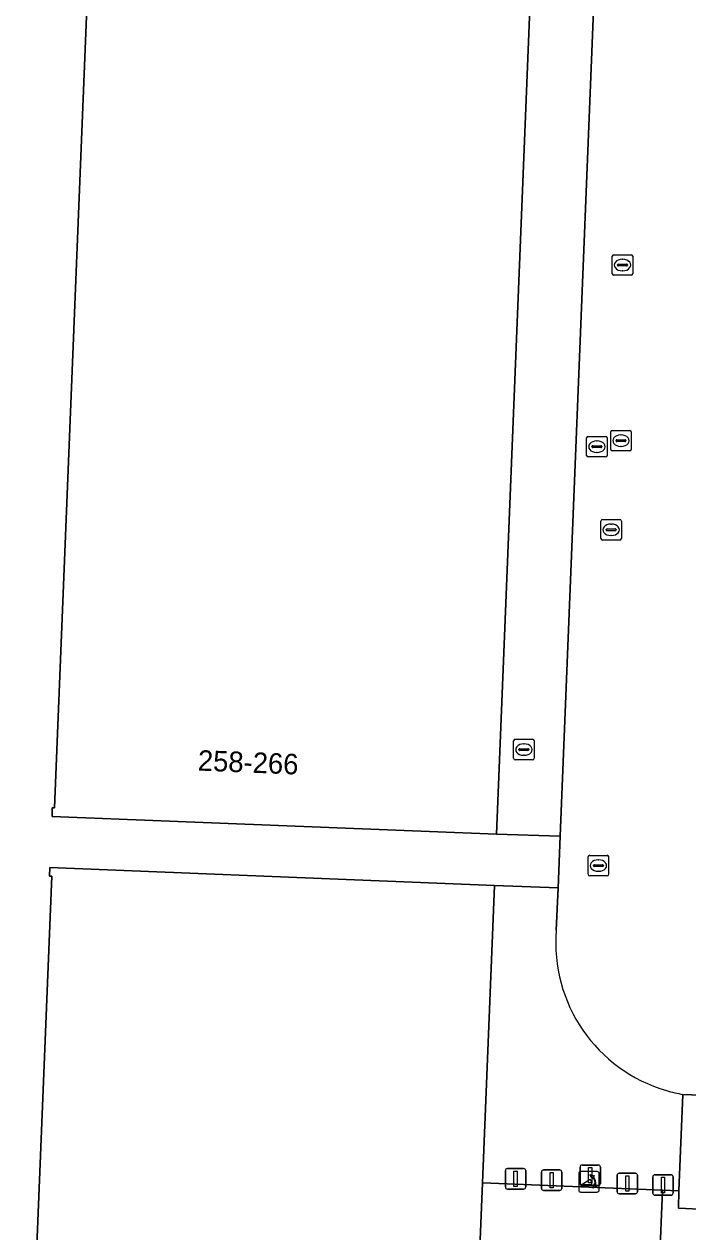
# Model space of a CAD drawing. Extents: x 160888 to 161385, y 386490 to 386908.
# Drawn here: x 161191.2 to 161223.6, y 386584.9 to 386643.8 of the extents above; entities that cross this region are included whole.
import ezdxf

# ---------------------------------------------------------------- set-up
doc = ezdxf.new("R2010")
doc.units = 0
for name, color, linetype in [('IMGEO_Afsluitpaal', 7, 'Continuous'), ('IMGEO_Brandkraan', 7, 'Continuous'), ('IMGEO_Groenvoorziening', 7, 'Continuous'), ('IMGEO_Haag', 7, 'Continuous'), ('IMGEO_Kolk', 7, 'Continuous'), ('IMGEO_Pand', 7, 'Continuous'), ('IMGEO_Pand_nummerreeks', 7, 'Continuous'), ('IMGEO_Poller', 7, 'Continuous'), ('IMGEO_Rijbaan_lokaal_open', 7, 'Continuous'), ('IMGEO_Rioolput', 7, 'Continuous'), ('IMGEO_Voetgangersgebied_open', 7, 'Continuous'), ('IMGEO_Voetpad_open', 7, 'Continuous')]:
    doc.layers.add(name, color=color, linetype=linetype)

msp = doc.modelspace()

# ---------------------------------------------------------------- linework, layer by layer
at = {"layer": 'IMGEO_Afsluitpaal'}
for p, q in [((161214.773, 386588.001), (161215.563, 386588.001)), ((161215.563, 386588.001), (161214.773, 386588.001)), ((161218.315, 386587.271), (161218.315, 386588.071)), ((161218.315, 386588.071), (161218.315, 386587.271)), ((161218.415, 386588.171), (161219.205, 386588.171)), ((161219.205, 386588.171), (161218.415, 386588.171)), ((161219.305, 386588.071), (161219.305, 386587.271)), ((161219.305, 386587.271), (161219.305, 386588.071)), ((161214.673, 386587.101), (161214.673, 386587.901)), ((161214.673, 386587.901), (161214.673, 386587.101)), ((161215.663, 386587.901), (161215.663, 386587.101)), ((161215.663, 386587.101), (161215.663, 386587.901)), ((161216.431, 386587.031), (161216.431, 386587.831)), ((161216.431, 386587.831), (161216.431, 386587.031)), ((161216.531, 386587.931), (161217.321, 386587.931)), ((161217.321, 386587.931), (161216.531, 386587.931)), ((161217.421, 386587.831), (161217.421, 386587.031)), ((161217.421, 386587.031), (161217.421, 386587.831)), ((161220.124, 386586.872), (161220.124, 386587.672)), ((161220.124, 386587.672), (161220.124, 386586.872)), ((161220.224, 386587.772), (161221.014, 386587.772)), ((161221.014, 386587.772), (161220.224, 386587.772)), ((161221.114, 386587.672), (161221.114, 386586.872)), ((161221.114, 386586.872), (161221.114, 386587.672)), ((161221.865, 386586.798), (161221.865, 386587.598)), ((161221.865, 386587.598), (161221.865, 386586.798)), ((161221.965, 386587.698), (161222.755, 386587.698)), ((161222.755, 386587.698), (161221.965, 386587.698)), ((161222.855, 386587.598), (161222.855, 386586.798)), ((161222.855, 386586.798), (161222.855, 386587.598)), ((161215.563, 386587.001), (161214.773, 386587.001)), ((161214.773, 386587.001), (161215.563, 386587.001)), ((161217.321, 386586.931), (161216.531, 386586.931)), ((161216.531, 386586.931), (161217.321, 386586.931)), ((161219.205, 386587.171), (161218.415, 386587.171)), ((161218.415, 386587.171), (161219.205, 386587.171)), ((161221.014, 386586.772), (161220.224, 386586.772)), ((161220.224, 386586.772), (161221.014, 386586.772)), ((161222.755, 386586.698), (161221.965, 386586.698)), ((161221.965, 386586.698), (161222.755, 386586.698))]:
    msp.add_line(p, q, dxfattribs=at)
for points in [[(161218.735, 386588.046), (161218.885, 386588.046), (161218.885, 386587.296), (161218.735, 386587.296), (161218.735, 386588.046)], [(161215.093, 386587.876), (161215.243, 386587.876), (161215.243, 386587.126), (161215.093, 386587.126), (161215.093, 386587.876)], [(161216.851, 386587.806), (161217.001, 386587.806), (161217.001, 386587.056), (161216.851, 386587.056), (161216.851, 386587.806)], [(161220.544, 386587.647), (161220.694, 386587.647), (161220.694, 386586.897), (161220.544, 386586.897), (161220.544, 386587.647)], [(161222.285, 386587.573), (161222.435, 386587.573), (161222.435, 386586.823), (161222.285, 386586.823), (161222.285, 386587.573)]]:
    msp.add_lwpolyline(points, dxfattribs=at)
for centre, start, end in [((161214.773, 386587.901), 90, 180), ((161214.773, 386587.901), 90, 180), ((161215.563, 386587.901), 0, 90), ((161215.563, 386587.901), 360, 90), ((161218.415, 386588.071), 90, 180), ((161218.415, 386588.071), 90, 180), ((161219.205, 386588.071), 0, 90), ((161219.205, 386588.071), 360, 90), ((161216.531, 386587.831), 90, 180), ((161216.531, 386587.831), 90, 180), ((161217.321, 386587.831), 0, 90), ((161217.321, 386587.831), 360, 90), ((161220.224, 386587.672), 90, 180), ((161220.224, 386587.672), 90, 180), ((161221.014, 386587.672), 0, 90), ((161221.014, 386587.672), 360, 90), ((161221.965, 386587.598), 90, 180), ((161221.965, 386587.598), 90, 180), ((161222.755, 386587.598), 0, 90), ((161222.755, 386587.598), 360, 90), ((161214.773, 386587.101), 180, 270), ((161214.773, 386587.101), 180, 270), ((161215.563, 386587.101), 270, 0), ((161215.563, 386587.101), 270, 0), ((161216.531, 386587.031), 180, 270), ((161216.531, 386587.031), 180, 270), ((161217.321, 386587.031), 270, 0), ((161217.321, 386587.031), 270, 0), ((161218.415, 386587.271), 180, 270), ((161218.415, 386587.271), 180, 270), ((161219.205, 386587.271), 270, 0), ((161219.205, 386587.271), 270, 0), ((161220.224, 386586.872), 180, 270), ((161220.224, 386586.872), 180, 270), ((161221.014, 386586.872), 270, 0), ((161221.014, 386586.872), 270, 0), ((161221.965, 386586.798), 180, 270), ((161221.965, 386586.798), 180, 270), ((161222.755, 386586.798), 270, 0), ((161222.755, 386586.798), 270, 0)]:
    msp.add_arc(centre, 0.1, start, end, dxfattribs=at)
at = {"layer": 'IMGEO_Brandkraan'}
for p, q in [((161215.075, 386608.011), (161215.075, 386608.863)), ((161215.15, 386608.937), (161216.002, 386608.937)), ((161215.563, 386608.717), (161215.588, 386608.717)), ((161216.076, 386608.863), (161216.076, 386608.011)), ((161215.334, 386608.431), (161215.334, 386608.443)), ((161215.772, 386608.394), (161215.374, 386608.394)), ((161215.377, 386608.48), (161215.775, 386608.48)), ((161215.586, 386608.157), (161215.561, 386608.157)), ((161215.818, 386608.443), (161215.818, 386608.431)), ((161216.002, 386607.937), (161215.15, 386607.937))]:
    msp.add_line(p, q, dxfattribs=at)
for points in [[(161215.075, 386608.011), (161215.075, 386608.863)], [(161215.15, 386608.937), (161216.002, 386608.937)], [(161216.076, 386608.863), (161216.076, 386608.011)], [(161216.002, 386607.937), (161215.15, 386607.937)]]:
    msp.add_lwpolyline(points, dxfattribs=at)
for centre, radius, start, end in [((161215.152, 386608.861), 0.0765, 91.55205, 178.44795), ((161215.152, 386608.861), 0.0765, 91.55205, 178.44795), ((161216, 386608.861), 0.0765, 1.55205, 88.44795), ((161216, 386608.861), 0.0765, 1.55205, 88.44795), ((161215.152, 386608.013), 0.0765, 181.55205, 268.44795), ((161215.152, 386608.013), 0.0765, 181.55205, 268.44795), ((161215.374, 386608.44), 0.0403, 85.87752, 175.75265), ((161215.371, 386608.43), 0.0366, 178.93798, 274.71019), ((161215.775, 386608.437), 0.043, 264.86636, 352.45326), ((161215.779, 386608.442), 0.0386, 1.73085, 96.63898), ((161216, 386608.013), 0.0765, 271.55205, 358.44795), ((161216, 386608.013), 0.0765, 271.55205, 358.44795)]:
    msp.add_arc(centre, radius, start, end, dxfattribs=at)
for centre, major_axis, ratio, start_param, end_param in [((161215.562, 386608.437), (-0.387, 0.002), 0.722429, 4.712389, 7.853982), ((161215.587, 386608.437), (-0.39, 0.002), 0.717154, 1.570796, 4.712389)]:
    msp.add_ellipse(centre, major_axis=major_axis, ratio=ratio, start_param=start_param, end_param=end_param, dxfattribs=at)
at = {"layer": 'IMGEO_Groenvoorziening'}
msp.add_lwpolyline([(161225.845, 386591.51), (161223.337, 386591.617), (161223.136, 386586.912), (161223.119, 386586.063), (161225.814, 386585.935), (161226.578, 386585.899), (161226.59, 386586.509)], dxfattribs=at)
at = {"layer": 'IMGEO_Haag'}
msp.add_lwpolyline([(161225.845, 386591.51), (161223.337, 386591.617), (161223.136, 386586.912), (161223.119, 386586.063), (161225.814, 386585.935), (161226.578, 386585.899), (161226.59, 386586.509)], dxfattribs=at)
at = {"layer": 'IMGEO_Kolk'}
for p, q in [((161219.886, 386631.645), (161219.886, 386632.497)), ((161219.961, 386632.571), (161220.813, 386632.571)), ((161220.374, 386632.351), (161220.399, 386632.351)), ((161220.887, 386632.497), (161220.887, 386631.645)), ((161220.145, 386632.065), (161220.145, 386632.077)), ((161220.583, 386632.028), (161220.185, 386632.028)), ((161220.188, 386632.114), (161220.586, 386632.114)), ((161220.397, 386631.791), (161220.372, 386631.791)), ((161220.629, 386632.077), (161220.629, 386632.065)), ((161220.813, 386631.571), (161219.961, 386631.571)), ((161219.331, 386618.732), (161219.331, 386619.584)), ((161219.406, 386619.658), (161220.258, 386619.658)), ((161219.633, 386619.201), (161220.031, 386619.201)), ((161219.819, 386619.438), (161219.844, 386619.438)), ((161220.332, 386619.584), (161220.332, 386618.732)), ((161220.258, 386618.658), (161219.406, 386618.658)), ((161219.59, 386619.152), (161219.59, 386619.164)), ((161220.028, 386619.115), (161219.63, 386619.115)), ((161219.842, 386618.878), (161219.817, 386618.878)), ((161220.074, 386619.164), (161220.074, 386619.152)), ((161218.71, 386602.352), (161218.71, 386603.204)), ((161218.785, 386603.278), (161219.637, 386603.278)), ((161218.969, 386602.772), (161218.969, 386602.784)), ((161219.407, 386602.735), (161219.009, 386602.735)), ((161219.012, 386602.821), (161219.41, 386602.821)), ((161219.198, 386603.058), (161219.223, 386603.058)), ((161219.453, 386602.784), (161219.453, 386602.772)), ((161219.711, 386603.204), (161219.711, 386602.352)), ((161219.637, 386602.278), (161218.785, 386602.278)), ((161219.221, 386602.498), (161219.196, 386602.498))]:
    msp.add_line(p, q, dxfattribs=at)
for points in [[(161219.886, 386631.645), (161219.886, 386632.497)], [(161219.961, 386632.571), (161220.813, 386632.571)], [(161220.887, 386632.497), (161220.887, 386631.645)], [(161220.813, 386631.571), (161219.961, 386631.571)], [(161219.331, 386618.732), (161219.331, 386619.584)], [(161219.406, 386619.658), (161220.258, 386619.658)], [(161220.332, 386619.584), (161220.332, 386618.732)], [(161220.258, 386618.658), (161219.406, 386618.658)], [(161218.71, 386602.352), (161218.71, 386603.204)], [(161218.785, 386603.278), (161219.637, 386603.278)], [(161219.711, 386603.204), (161219.711, 386602.352)], [(161219.637, 386602.278), (161218.785, 386602.278)]]:
    msp.add_lwpolyline(points, dxfattribs=at)
for centre, radius, start, end in [((161219.963, 386632.495), 0.0765, 91.55205, 178.44795), ((161219.963, 386632.495), 0.0765, 91.55205, 178.44795), ((161220.811, 386632.495), 0.0765, 1.55205, 88.44795), ((161220.811, 386632.495), 0.0765, 1.55205, 88.44795), ((161219.963, 386631.647), 0.0765, 181.55205, 268.44795), ((161219.963, 386631.647), 0.0765, 181.55205, 268.44795), ((161220.185, 386632.074), 0.0403, 85.87752, 175.75265), ((161220.182, 386632.064), 0.0366, 178.93798, 274.71019), ((161220.586, 386632.071), 0.043, 264.86636, 352.45326), ((161220.59, 386632.076), 0.0386, 1.73085, 96.63898), ((161220.811, 386631.647), 0.0765, 271.55205, 358.44795), ((161220.811, 386631.647), 0.0765, 271.55205, 358.44795), ((161219.408, 386619.582), 0.0765, 91.55205, 178.44795), ((161219.408, 386619.582), 0.0765, 91.55205, 178.44795), ((161219.63, 386619.161), 0.0403, 85.87752, 175.75265), ((161220.035, 386619.163), 0.0386, 1.73085, 96.63898), ((161220.256, 386619.582), 0.0765, 1.55205, 88.44795), ((161220.256, 386619.582), 0.0765, 1.55205, 88.44795), ((161219.408, 386618.734), 0.0765, 181.55205, 268.44795), ((161219.408, 386618.734), 0.0765, 181.55205, 268.44795), ((161219.627, 386619.151), 0.0366, 178.93798, 274.71019), ((161220.031, 386619.158), 0.043, 264.86636, 352.45326), ((161220.256, 386618.734), 0.0765, 271.55205, 358.44795), ((161220.256, 386618.734), 0.0765, 271.55205, 358.44795), ((161218.787, 386603.202), 0.0765, 91.55205, 178.44795), ((161218.787, 386603.202), 0.0765, 91.55205, 178.44795), ((161219.009, 386602.781), 0.0403, 85.87752, 175.75265), ((161219.006, 386602.771), 0.0366, 178.93798, 274.71019), ((161219.41, 386602.778), 0.043, 264.86636, 352.45326), ((161219.414, 386602.783), 0.0386, 1.73085, 96.63898), ((161219.635, 386603.202), 0.0765, 1.55205, 88.44795), ((161219.635, 386603.202), 0.0765, 1.55205, 88.44795), ((161218.787, 386602.354), 0.0765, 181.55205, 268.44795), ((161218.787, 386602.354), 0.0765, 181.55205, 268.44795), ((161219.635, 386602.354), 0.0765, 271.55205, 358.44795), ((161219.635, 386602.354), 0.0765, 271.55205, 358.44795)]:
    msp.add_arc(centre, radius, start, end, dxfattribs=at)
for centre, major_axis, ratio, start_param, end_param in [((161220.373, 386632.071), (-0.387, 0.002), 0.722429, 4.712389, 7.853982), ((161220.398, 386632.071), (-0.39, 0.002), 0.717154, 1.570796, 4.712389), ((161219.818, 386619.158), (-0.387, 0.002), 0.722429, 4.712389, 7.853982), ((161219.843, 386619.158), (-0.39, 0.002), 0.717154, 1.570796, 4.712389), ((161219.197, 386602.778), (-0.387, 0.002), 0.722429, 4.712389, 7.853982), ((161219.222, 386602.778), (-0.39, 0.002), 0.717154, 1.570796, 4.712389)]:
    msp.add_ellipse(centre, major_axis=major_axis, ratio=ratio, start_param=start_param, end_param=end_param, dxfattribs=at)
at = {"layer": 'IMGEO_Pand'}
for points in [[(161194.188, 386645.434), (161194.288, 386645.43), (161192.672, 386605.589), (161192.572, 386605.592), (161192.56, 386605.179), (161214.242, 386604.304), (161215.889, 386644.972), (161194.205, 386645.849)], [(161191.198, 386569.006), (161204.671, 386568.461), (161212.673, 386568.138), (161213.252, 386579.772), (161213.556, 386587.296), (161214.141, 386601.806), (161192.456, 386602.678), (161192.441, 386602.269), (161192.541, 386602.265)]]:
    msp.add_lwpolyline(points, close=True, dxfattribs=at)
at = {"layer": 'IMGEO_Poller'}
for p, q in [((161218.251, 386587.758), (161218.251, 386586.951)), ((161218.251, 386587.758), (161218.251, 386586.951)), ((161219.153, 386587.853), (161218.345, 386587.853)), ((161219.153, 386587.853), (161218.345, 386587.853)), ((161219.247, 386586.951), (161219.247, 386587.758)), ((161219.247, 386586.951), (161219.247, 386587.758)), ((161218.345, 386586.856), (161219.153, 386586.856)), ((161218.345, 386586.856), (161219.153, 386586.856))]:
    msp.add_line(p, q, dxfattribs=at)
for points in [[(161218.886, 386587.209), (161218.373, 386587.209), (161218.803, 386587.484)], [(161218.93, 386587.582), (161218.918, 386587.509), (161218.793, 386587.714)], [(161218.793, 386587.714), (161219.024, 386587.648), (161218.953, 386587.616)], [(161218.946, 386587.037), (161219.012, 386587.268), (161219.042, 386587.2)], [(161219.078, 386587.173), (161219.15, 386587.162), (161218.946, 386587.037)]]:
    msp.add_lwpolyline(points, dxfattribs=at)
for centre, radius, start, end in [((161218.345, 386587.758), 0.0946, 90, 180), ((161218.345, 386587.758), 0.0946, 90, 180), ((161218.558, 386587.259), 0.332, 351.32473, 42.4854), ((161218.572, 386587.269), 0.476, 351.75274, 41.16905), ((161218.572, 386587.269), 0.516, 349.35686, 42.29123), ((161219.153, 386587.758), 0.0946, 0, 90), ((161219.153, 386587.758), 0.0946, 0, 90), ((161218.345, 386586.951), 0.0946, 180, 270), ((161218.345, 386586.951), 0.0946, 180, 270), ((161219.153, 386586.951), 0.0946, 270, 0), ((161219.153, 386586.951), 0.0946, 270, 0)]:
    msp.add_arc(centre, radius, start, end, dxfattribs=at)
at = {"layer": 'IMGEO_Rijbaan_lokaal_open'}
for points in [[(161219.977, 386669.302), (161219.091, 386647.411), (161218.989, 386644.89), (161217.342, 386604.22), (161217.24, 386601.701), (161217.156, 386599.626)], [(161223.337, 386591.617), (161225.845, 386591.51), (161236.29, 386591.113), (161238.207, 386591.047), (161244.276, 386590.775), (161248.771, 386590.62), (161250.704, 386590.546), (161252.339, 386590.479), (161258.277, 386590.35), (161258.463, 386596.234), (161254.664, 386596.392), (161234.495, 386597.192), (161230, 386597.363)]]:
    msp.add_lwpolyline(points, dxfattribs=at)
for centre, radius, start, end in [((161224.629, 386599.004), 7.499, 175.24232, 253.73554), ((161224.643, 386599.059), 7.556, 253.75499, 260.04871)]:
    msp.add_arc(centre, radius, start, end, dxfattribs=at)
at = {"layer": 'IMGEO_Rioolput'}
for p, q in [((161219.81, 386623.079), (161219.81, 386623.931)), ((161219.885, 386624.005), (161220.737, 386624.005)), ((161220.811, 386623.931), (161220.811, 386623.079)), ((161218.636, 386622.786), (161218.636, 386623.638)), ((161218.711, 386623.712), (161219.563, 386623.712)), ((161219.124, 386623.492), (161219.149, 386623.492)), ((161219.637, 386623.638), (161219.637, 386622.786)), ((161220.069, 386623.499), (161220.069, 386623.511)), ((161220.507, 386623.462), (161220.109, 386623.462)), ((161220.112, 386623.548), (161220.51, 386623.548)), ((161220.298, 386623.785), (161220.323, 386623.785)), ((161220.553, 386623.511), (161220.553, 386623.499)), ((161218.895, 386623.206), (161218.895, 386623.218)), ((161219.333, 386623.169), (161218.935, 386623.169)), ((161218.938, 386623.255), (161219.336, 386623.255)), ((161219.147, 386622.932), (161219.122, 386622.932)), ((161219.379, 386623.218), (161219.379, 386623.206)), ((161220.737, 386623.005), (161219.885, 386623.005)), ((161220.321, 386623.225), (161220.296, 386623.225)), ((161219.563, 386622.712), (161218.711, 386622.712))]:
    msp.add_line(p, q, dxfattribs=at)
for points in [[(161219.81, 386623.079), (161219.81, 386623.931)], [(161219.885, 386624.005), (161220.737, 386624.005)], [(161220.811, 386623.931), (161220.811, 386623.079)], [(161218.636, 386622.786), (161218.636, 386623.638)], [(161218.711, 386623.712), (161219.563, 386623.712)], [(161219.637, 386623.638), (161219.637, 386622.786)], [(161220.737, 386623.005), (161219.885, 386623.005)], [(161219.563, 386622.712), (161218.711, 386622.712)]]:
    msp.add_lwpolyline(points, dxfattribs=at)
for centre, radius, start, end in [((161219.887, 386623.929), 0.0765, 91.55205, 178.44795), ((161219.887, 386623.929), 0.0765, 91.55205, 178.44795), ((161220.735, 386623.929), 0.0765, 1.55205, 88.44795), ((161220.735, 386623.929), 0.0765, 1.55205, 88.44795), ((161218.713, 386623.636), 0.0765, 91.55205, 178.44795), ((161218.713, 386623.636), 0.0765, 91.55205, 178.44795), ((161219.561, 386623.636), 0.0765, 1.55205, 88.44795), ((161219.561, 386623.636), 0.0765, 1.55205, 88.44795), ((161220.109, 386623.508), 0.0403, 85.87752, 175.75265), ((161220.106, 386623.498), 0.0366, 178.93798, 274.71019), ((161220.51, 386623.505), 0.043, 264.86636, 352.45326), ((161220.514, 386623.51), 0.0386, 1.73085, 96.63898), ((161218.713, 386622.788), 0.0765, 181.55205, 268.44795), ((161218.713, 386622.788), 0.0765, 181.55205, 268.44795), ((161218.935, 386623.215), 0.0403, 85.87752, 175.75265), ((161218.932, 386623.205), 0.0366, 178.93798, 274.71019), ((161219.336, 386623.212), 0.043, 264.86636, 352.45326), ((161219.34, 386623.217), 0.0386, 1.73085, 96.63898), ((161219.561, 386622.788), 0.0765, 271.55205, 358.44795), ((161219.561, 386622.788), 0.0765, 271.55205, 358.44795), ((161219.887, 386623.081), 0.0765, 181.55205, 268.44795), ((161219.887, 386623.081), 0.0765, 181.55205, 268.44795), ((161220.735, 386623.081), 0.0765, 271.55205, 358.44795), ((161220.735, 386623.081), 0.0765, 271.55205, 358.44795)]:
    msp.add_arc(centre, radius, start, end, dxfattribs=at)
for centre, major_axis, ratio, start_param, end_param in [((161219.123, 386623.212), (-0.387, 0.002), 0.722429, 4.712389, 7.853982), ((161219.148, 386623.212), (-0.39, 0.002), 0.717154, 1.570796, 4.712389), ((161220.297, 386623.505), (-0.387, 0.002), 0.722429, 4.712389, 7.853982), ((161220.322, 386623.505), (-0.39, 0.002), 0.717154, 1.570796, 4.712389)]:
    msp.add_ellipse(centre, major_axis=major_axis, ratio=ratio, start_param=start_param, end_param=end_param, dxfattribs=at)
at = {"layer": 'IMGEO_Voetgangersgebied_open'}
for points in [[(161191.198, 386569.006), (161192.541, 386602.265), (161192.441, 386602.269), (161192.456, 386602.678), (161214.141, 386601.806), (161217.24, 386601.701), (161217.342, 386604.22), (161214.242, 386604.304), (161192.56, 386605.179), (161192.572, 386605.592), (161192.672, 386605.589), (161194.288, 386645.43), (161194.188, 386645.434), (161194.205, 386645.849), (161215.889, 386644.972), (161218.989, 386644.89), (161219.091, 386647.411), (161216.005, 386647.458), (161194.302, 386648.347), (161194.32, 386648.757), (161194.42, 386648.752), (161196.801, 386707.775)], [(161222.191, 386583.404), (161222.333, 386586.944), (161213.556, 386587.296), (161213.252, 386579.772)]]:
    msp.add_lwpolyline(points, dxfattribs=at)
at = {"layer": 'IMGEO_Voetpad_open'}
for points in [[(161214.242, 386604.304), (161217.342, 386604.22), (161218.989, 386644.89), (161215.889, 386644.972)], [(161251.571, 386584.9), (161226.578, 386585.899), (161225.814, 386585.935), (161223.119, 386586.063), (161223.136, 386586.912), (161222.333, 386586.944), (161222.191, 386583.404), (161251.461, 386582.195)]]:
    msp.add_lwpolyline(points, close=True, dxfattribs=at)
msp.add_lwpolyline([(161217.156, 386599.626), (161217.24, 386601.701), (161214.141, 386601.806), (161213.556, 386587.296), (161222.333, 386586.944), (161223.136, 386586.912), (161223.337, 386591.617)], dxfattribs=at)
for centre, radius, start, end in [((161224.629, 386599.004), 7.499, 175.24232, 253.73554), ((161224.643, 386599.059), 7.556, 253.75499, 260.04871)]:
    msp.add_arc(centre, radius, start, end, dxfattribs=at)

# ---------------------------------------------------------------- texts
at = {"layer": 'IMGEO_Pand_nummerreeks'}
msp.add_text('258-266', height=1, rotation=357.68902, dxfattribs=at).set_placement((161199.656, 386607.415))

doc.saveas('drawing.dxf')
